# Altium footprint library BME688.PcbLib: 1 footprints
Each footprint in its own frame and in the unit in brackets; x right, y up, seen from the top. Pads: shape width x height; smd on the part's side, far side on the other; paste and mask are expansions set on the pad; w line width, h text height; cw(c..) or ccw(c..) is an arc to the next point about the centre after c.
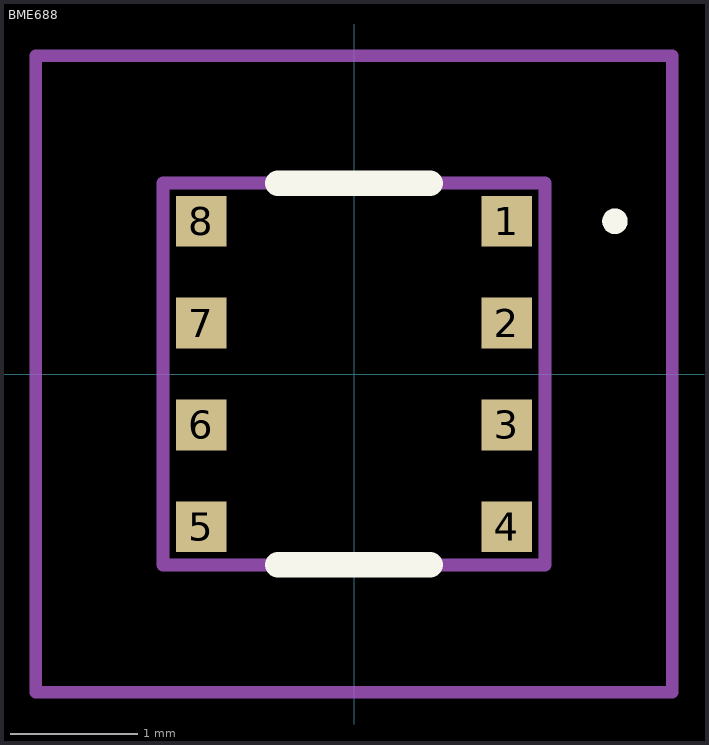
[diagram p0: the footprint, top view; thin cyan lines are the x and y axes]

## BME688 [mm]
pads (8):
  rect 0.4x0.4 smd: 1(1.2,1.2) 2(1.2,0.4) 3(1.2,-0.4) 4(1.2,-1.2) 5(-1.2,-1.2) 6(-1.2,-0.4) 7(-1.2,0.4) 8(-1.2,1.2)
Top Overlay:
  lines w0.1: 2,1.2 cw(c2.05,1.2) 2.1,1.2 ; 2,1.2 2,1.2 ; 2,1.2 ccw(c2.05,1.2) 2.1,1.2 ; 2.1,1.2 2.1,1.2
  lines w0.2: -0.6,-1.5 0.6,-1.5 ; -0.6,1.5 0.6,1.5
Mechanical 15:
  lines w0.1: -1.5,-1.5 1.5,-1.5 1.5,1.5 -1.5,1.5 -1.5,-1.5
Mechanical 20:
  lines w0.1: -2.5,-2.5 2.5,-2.5 2.5,2.5 -2.5,2.5 -2.5,-2.5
